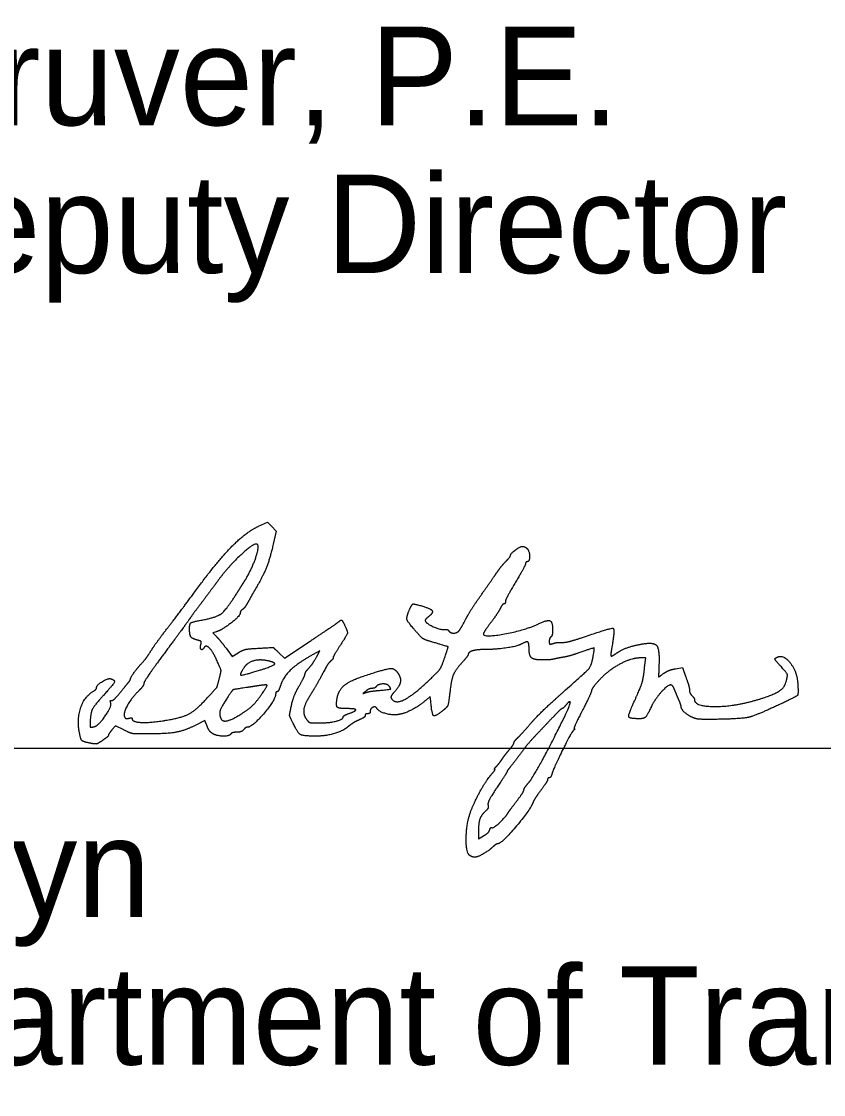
# Model space of a CAD drawing. Extents: x 0 to 34, y 0 to 22.
# Drawn here: x 25.648 to 26.788, y 7.199 to 8.723 of the extents above; entities that cross this region are included whole.
import ezdxf

# ---------------------------------------------------------------- set-up
doc = ezdxf.new("R2010")
doc.units = 0
doc.layers.add('SH_Data', color=7, linetype='Continuous')
doc.layers.add('SH_Text', color=7, linetype='Continuous')

msp = doc.modelspace()

# ---------------------------------------------------------------- linework, layer by layer
at = {"layer": 'SH_Data'}
msp.add_line((24.5, 7.691), (28, 7.691), dxfattribs=at)
at = {"layer": 'SH_Text'}
for points in [[(25.9853, 8.0062), (25.9979, 8.012), (26.0042, 8.0057), (26.0106, 7.9993), (26.0062, 7.9806)], [(25.9253, 7.8562), (25.9203, 7.8546), (25.9255, 7.8495)], [(26.0143, 7.8265), (26.0224, 7.8189), (26.0587, 7.843)], [(25.9392, 7.8328), (25.9477, 7.8213), (25.9565, 7.8265)], [(26.0682, 7.8212), (26.0726, 7.8292), (26.0671, 7.8263)], [(26.534, 7.8053), (26.5355, 7.8191), (26.5277, 7.8191)], [(26.5779, 7.8037), (26.5876, 7.8053), (26.5926, 7.7917)], [(26.23, 7.7576), (26.2293, 7.7644), (26.2234, 7.7593)], [(25.7937, 7.7169), (25.7822, 7.7227), (25.7771, 7.7169)], [(25.9123, 7.722), (25.909, 7.73), (25.8951, 7.7231)], [(26.2977, 7.5714), (26.2977, 7.5621), (26.3052, 7.5664)]]:
    msp.add_lwpolyline(points, dxfattribs=at)
for points in [[(25.8957, 7.9143), (25.9254, 7.9549), (25.9672, 7.9978), (25.9853, 8.0062)], [(25.9838, 7.9804), (25.9802, 7.984), (25.9416, 7.9483), (25.9262, 7.927)], [(25.9655, 7.9283), (25.9749, 7.9432), (25.9869, 7.9773), (25.9838, 7.9804)], [(26.0062, 7.9806), (26.0012, 7.9595), (25.992, 7.9359), (25.9826, 7.9199)], [(26.3433, 7.9643), (26.3433, 7.9671), (26.3565, 7.9774), (26.3602, 7.9775)], [(26.3602, 7.9775), (26.3623, 7.9775), (26.3652, 7.9762), (26.3668, 7.9747)], [(26.3668, 7.9747), (26.3703, 7.9712), (26.3707, 7.9559), (26.3673, 7.9559)], [(26.3367, 7.9562), (26.3403, 7.9598), (26.3433, 7.9634), (26.3433, 7.9643)], [(26.3229, 7.9389), (26.3269, 7.9448), (26.3331, 7.9525), (26.3367, 7.9562)], [(26.3649, 7.9534), (26.3649, 7.952), (26.3584, 7.9399), (26.3505, 7.9266)], [(26.3673, 7.9559), (26.366, 7.9559), (26.3649, 7.9548), (26.3649, 7.9534)], [(25.955, 7.9117), (25.9583, 7.9169), (25.963, 7.9244), (25.9655, 7.9283)], [(26.3013, 7.9079), (26.3092, 7.9192), (26.319, 7.9331), (26.3229, 7.9389)], [(25.8555, 7.8609), (25.8644, 7.8722), (25.8825, 7.8963), (25.8957, 7.9143)], [(25.9262, 7.927), (25.9226, 7.9221), (25.9132, 7.9094), (25.9053, 7.8989)], [(25.9826, 7.9199), (25.9791, 7.914), (25.9739, 7.9048), (25.971, 7.8995)], [(26.3505, 7.9266), (26.3426, 7.9132), (26.3361, 7.9008), (26.3361, 7.8991)], [(25.9053, 7.8989), (25.8974, 7.8884), (25.8893, 7.8774), (25.8873, 7.8745)], [(25.9052, 7.873), (25.9258, 7.8768), (25.9398, 7.8877), (25.955, 7.9117)], [(25.971, 7.8995), (25.9682, 7.8943), (25.9644, 7.8891), (25.9626, 7.888)], [(26.2799, 7.8743), (26.2837, 7.8816), (26.2933, 7.8967), (26.3013, 7.9079)], [(26.3361, 7.8991), (26.3361, 7.8973), (26.3352, 7.8959), (26.3341, 7.8959)], [(25.9593, 7.8826), (25.9593, 7.8788), (25.9335, 7.8588), (25.9253, 7.8562)], [(25.9626, 7.888), (25.9608, 7.887), (25.9593, 7.8845), (25.9593, 7.8826)], [(26.209, 7.8568), (26.1975, 7.8698), (26.1953, 7.8766), (26.1992, 7.8862)], [(26.1992, 7.8862), (26.203, 7.8952), (26.2061, 7.8963), (26.2188, 7.8925)], [(26.2188, 7.8925), (26.2308, 7.889), (26.2337, 7.8828), (26.226, 7.8769)], [(26.3288, 7.8893), (26.3271, 7.8857), (26.3209, 7.8766), (26.3152, 7.8691)], [(26.3341, 7.8959), (26.333, 7.8959), (26.3306, 7.893), (26.3288, 7.8893)], [(25.8873, 7.8745), (25.8853, 7.8715), (25.87, 7.8506), (25.8532, 7.8279)], [(25.8873, 7.8609), (25.8873, 7.8677), (25.8914, 7.8705), (25.9052, 7.873)], [(26.0587, 7.843), (26.0786, 7.8563), (26.0962, 7.8682), (26.0978, 7.8695)], [(26.0978, 7.8695), (26.1023, 7.8733), (26.1047, 7.8724), (26.1077, 7.8658)], [(26.226, 7.8769), (26.2233, 7.8749), (26.2218, 7.872), (26.2228, 7.8707)], [(26.2228, 7.8707), (26.2254, 7.8669), (26.2453, 7.8587), (26.25, 7.8595)], [(26.2706, 7.8581), (26.2719, 7.8598), (26.2761, 7.8671), (26.2799, 7.8743)], [(26.3152, 7.8691), (26.3096, 7.8617), (26.3049, 7.8544), (26.3049, 7.8531)], [(26.3825, 7.8673), (26.3955, 7.8735), (26.4033, 7.8703), (26.4033, 7.8589)], [(25.834, 7.8315), (25.837, 7.8363), (25.8467, 7.8495), (25.8555, 7.8609)], [(25.8983, 7.8445), (25.8911, 7.8463), (25.8873, 7.852), (25.8873, 7.8609)], [(26.1077, 7.8658), (26.1121, 7.8562), (26.1111, 7.8521), (26.1009, 7.8362)], [(26.2325, 7.8416), (26.2217, 7.8447), (26.2168, 7.8479), (26.209, 7.8568)], [(26.25, 7.8595), (26.2522, 7.8599), (26.2548, 7.859), (26.2556, 7.8577)], [(26.2556, 7.8577), (26.2578, 7.8542), (26.2678, 7.8545), (26.2706, 7.8581)], [(26.3049, 7.8531), (26.3049, 7.8478), (26.3645, 7.8587), (26.3825, 7.8673)], [(26.4033, 7.8589), (26.4033, 7.8544), (26.4022, 7.85), (26.4009, 7.8491)], [(26.4456, 7.8482), (26.486, 7.8621), (26.4919, 7.8605), (26.4878, 7.8366)], [(25.9034, 7.8382), (25.9043, 7.8418), (25.9031, 7.8433), (25.8983, 7.8445)], [(25.9077, 7.8335), (25.9052, 7.8296), (25.902, 7.8331), (25.9034, 7.8382)], [(25.9255, 7.8495), (25.9283, 7.8467), (25.9345, 7.8392), (25.9392, 7.8328)], [(26.2493, 7.8179), (26.255, 7.8347), (26.2546, 7.8353), (26.2325, 7.8416)], [(26.3583, 7.8385), (26.3527, 7.8355), (26.3225, 7.8311), (26.3075, 7.8311)], [(26.3697, 7.8338), (26.3697, 7.8411), (26.366, 7.8427), (26.3583, 7.8385)], [(26.4009, 7.8491), (26.3996, 7.8483), (26.3985, 7.8455), (26.3985, 7.8428)], [(26.3985, 7.8428), (26.3985, 7.8389), (26.3995, 7.8383), (26.4039, 7.8397)], [(26.4039, 7.8397), (26.4069, 7.8407), (26.4127, 7.8413), (26.4168, 7.8412)], [(26.4168, 7.8412), (26.421, 7.841), (26.4339, 7.8442), (26.4456, 7.8482)], [(26.4938, 7.8257), (26.501, 7.8308), (26.5192, 7.8371), (26.5329, 7.8393)], [(26.5329, 7.8393), (26.5476, 7.8416), (26.5552, 7.8311), (26.5544, 7.8099)], [(25.8177, 7.8096), (25.8243, 7.8169), (25.8285, 7.8227), (25.834, 7.8315)], [(25.8532, 7.8279), (25.8364, 7.8053), (25.8226, 7.7851), (25.8225, 7.7831)], [(25.9265, 7.8149), (25.9203, 7.8285), (25.9106, 7.8382), (25.9077, 7.8335)], [(25.9565, 7.8265), (25.963, 7.8304), (25.9706, 7.8321), (25.9857, 7.8329)], [(25.9857, 7.8329), (26.006, 7.8341), (26.0062, 7.8341), (26.0143, 7.8265)], [(26.0671, 7.8263), (26.0437, 7.8137), (26.021, 7.793), (26.0168, 7.7806)], [(26.1009, 7.8362), (26.0956, 7.8281), (26.0913, 7.8205), (26.0913, 7.8194)], [(26.2833, 7.824), (26.2833, 7.8231), (26.2791, 7.8177), (26.2739, 7.8119)], [(26.3075, 7.8311), (26.296, 7.8311), (26.2833, 7.8274), (26.2833, 7.824)], [(26.389, 7.8162), (26.3766, 7.8162), (26.3697, 7.8225), (26.3697, 7.8338)], [(26.4403, 7.8262), (26.4325, 7.8235), (26.4229, 7.8208), (26.4189, 7.8202)], [(26.4609, 7.8216), (26.463, 7.8331), (26.4613, 7.8335), (26.4403, 7.8262)], [(26.4878, 7.8366), (26.4865, 7.829), (26.4857, 7.8224), (26.4862, 7.8219)], [(26.4862, 7.8219), (26.4867, 7.8214), (26.4901, 7.8231), (26.4938, 7.8257)], [(25.8033, 7.7891), (25.8033, 7.7908), (25.8124, 7.8038), (25.8177, 7.8096)], [(25.9298, 7.7903), (25.9323, 7.8002), (25.932, 7.8024), (25.9265, 7.8149)], [(25.9975, 7.8152), (25.9866, 7.8174), (25.9693, 7.8123), (25.9649, 7.8057)], [(25.9869, 7.8017), (26.0061, 7.8076), (26.0101, 7.8127), (25.9975, 7.8152)], [(26.0554, 7.8031), (26.0608, 7.8091), (26.0633, 7.8127), (26.0682, 7.8212)], [(26.0877, 7.8144), (26.0858, 7.8128), (26.0827, 7.8086), (26.0809, 7.8051)], [(26.0913, 7.8194), (26.0913, 7.8182), (26.0897, 7.816), (26.0877, 7.8144)], [(26.231, 7.7906), (26.2414, 7.8006), (26.2455, 7.8068), (26.2493, 7.8179)], [(26.2739, 7.8119), (26.2655, 7.8024), (26.2597, 7.7899), (26.2581, 7.7771)], [(26.4057, 7.8176), (26.4024, 7.8168), (26.3949, 7.8162), (26.389, 7.8162)], [(26.4189, 7.8202), (26.4149, 7.8195), (26.409, 7.8184), (26.4057, 7.8176)], [(26.4161, 7.7686), (26.4516, 7.8002), (26.4585, 7.8083), (26.4609, 7.8216)], [(26.5277, 7.8191), (26.515, 7.8191), (26.4812, 7.8007), (26.4691, 7.7872)], [(26.5544, 7.8099), (26.5537, 7.7915), (26.5536, 7.7918), (26.5613, 7.7973)], [(26.7245, 7.8105), (26.7192, 7.8162), (26.719, 7.8189), (26.7236, 7.8206)], [(26.7236, 7.8206), (26.7322, 7.8239), (26.7506, 7.799), (26.7516, 7.7827)], [(26.7336, 7.7814), (26.7376, 7.7932), (26.736, 7.7981), (26.7245, 7.8105)], [(25.9649, 7.8057), (25.9579, 7.795), (25.9625, 7.7942), (25.9869, 7.8017)], [(26.0429, 7.779), (26.0473, 7.7867), (26.0512, 7.7943), (26.0514, 7.7961)], [(26.0514, 7.7961), (26.0517, 7.7978), (26.0535, 7.801), (26.0554, 7.8031)], [(26.0809, 7.8051), (26.0727, 7.7897), (26.0649, 7.7759), (26.0588, 7.7662)], [(26.0971, 7.7623), (26.0992, 7.7736), (26.1154, 7.787), (26.1347, 7.7934)], [(26.1347, 7.7934), (26.1665, 7.804), (26.1799, 7.8044), (26.185, 7.7949)], [(26.185, 7.7949), (26.1882, 7.7889), (26.1848, 7.7775), (26.1774, 7.7696)], [(26.5194, 7.7575), (26.5284, 7.7774), (26.5324, 7.7906), (26.534, 7.8053)], [(26.5613, 7.7973), (26.5651, 7.8), (26.5726, 7.8029), (26.5779, 7.8037)], [(26.5926, 7.7917), (26.5954, 7.7843), (26.5977, 7.7761), (26.5977, 7.7736)], [(25.7506, 7.7718), (25.7532, 7.7734), (25.7553, 7.7758), (25.7553, 7.7771)], [(25.7553, 7.7771), (25.7554, 7.7809), (25.7721, 7.7908), (25.7759, 7.7894)], [(25.7759, 7.7894), (25.7819, 7.7871), (25.7796, 7.7822), (25.7653, 7.7663)], [(25.7888, 7.7699), (25.7941, 7.7765), (25.7996, 7.7832), (25.8009, 7.7848)], [(25.8009, 7.7848), (25.8022, 7.7864), (25.8033, 7.7884), (25.8033, 7.7891)], [(25.8225, 7.7831), (25.8224, 7.7812), (25.8191, 7.7763), (25.8151, 7.7724)], [(25.9101, 7.7598), (25.9262, 7.7774), (25.9265, 7.7779), (25.9298, 7.7903)], [(25.9677, 7.7769), (25.9499, 7.7743), (25.9479, 7.7732), (25.9406, 7.762)], [(25.9851, 7.7796), (25.9795, 7.7787), (25.9717, 7.7775), (25.9677, 7.7769)], [(25.9901, 7.7679), (25.9979, 7.7793), (25.997, 7.7814), (25.9851, 7.7796)], [(26.0168, 7.7806), (26.0151, 7.7754), (26.0128, 7.7711), (26.0117, 7.7711)], [(26.032, 7.7512), (26.0336, 7.7589), (26.0385, 7.7714), (26.0429, 7.779)], [(26.1468, 7.7759), (26.1445, 7.7759), (26.1405, 7.7742), (26.138, 7.7721)], [(26.1523, 7.7781), (26.1516, 7.7769), (26.1491, 7.7759), (26.1468, 7.7759)], [(26.1708, 7.7792), (26.168, 7.7825), (26.1546, 7.7817), (26.1523, 7.7781)], [(26.1549, 7.7728), (26.1716, 7.7743), (26.174, 7.7753), (26.1708, 7.7792)], [(26.174, 7.7617), (26.1793, 7.7531), (26.2061, 7.7666), (26.231, 7.7906)], [(26.2581, 7.7771), (26.2553, 7.7546), (26.2536, 7.7492), (26.2479, 7.7447)], [(26.4691, 7.7872), (26.4632, 7.7807), (26.4585, 7.7741), (26.4585, 7.7726)], [(26.5709, 7.7807), (26.5666, 7.7807), (26.5483, 7.7602), (26.5436, 7.7501)], [(26.5765, 7.7741), (26.575, 7.7778), (26.5725, 7.7807), (26.5709, 7.7807)], [(26.6847, 7.7571), (26.7084, 7.7634), (26.7314, 7.7748), (26.7336, 7.7814)], [(26.7516, 7.7827), (26.7526, 7.7674), (26.7499, 7.7643), (26.7265, 7.7533)], [(25.7304, 7.7155), (25.7275, 7.734), (25.7382, 7.764), (25.7506, 7.7718)], [(25.7653, 7.7663), (25.7516, 7.7511), (25.7466, 7.741), (25.746, 7.7272)], [(25.7765, 7.7586), (25.7779, 7.7583), (25.7834, 7.7633), (25.7888, 7.7699)], [(25.8151, 7.7724), (25.8053, 7.7628), (25.7929, 7.7407), (25.7947, 7.736)], [(25.9406, 7.762), (25.9324, 7.7493), (25.9292, 7.7395), (25.9315, 7.7337)], [(25.9602, 7.7392), (25.9714, 7.7462), (25.9824, 7.7567), (25.9901, 7.7679)], [(26.0097, 7.7681), (26.0095, 7.7596), (25.9764, 7.7207), (25.9693, 7.7207)], [(26.0117, 7.7711), (26.0106, 7.7711), (26.0097, 7.7698), (26.0097, 7.7681)], [(26.0588, 7.7662), (26.0508, 7.7536), (26.0486, 7.7384), (26.0537, 7.7316)], [(26.1106, 7.7471), (26.0991, 7.7471), (26.0951, 7.7517), (26.0971, 7.7623)], [(26.138, 7.7721), (26.1334, 7.7684), (26.1334, 7.7684), (26.1381, 7.77)], [(26.1381, 7.77), (26.1407, 7.771), (26.1483, 7.7722), (26.1549, 7.7728)], [(26.1774, 7.7696), (26.1746, 7.7667), (26.1731, 7.7631), (26.174, 7.7617)], [(26.372, 7.7259), (26.3792, 7.7343), (26.399, 7.7535), (26.4161, 7.7686)], [(26.4585, 7.7726), (26.4585, 7.771), (26.4525, 7.7581), (26.4453, 7.744)], [(26.5824, 7.76), (26.5806, 7.7641), (26.578, 7.7705), (26.5765, 7.7741)], [(26.5977, 7.7736), (26.5977, 7.7711), (26.5993, 7.7675), (26.6013, 7.7655)], [(26.6013, 7.7655), (26.6033, 7.7635), (26.6049, 7.7608), (26.6049, 7.7595)], [(25.7509, 7.7212), (25.7572, 7.7221), (25.7773, 7.7505), (25.7753, 7.7557)], [(25.7753, 7.7557), (25.7745, 7.7577), (25.7751, 7.759), (25.7765, 7.7586)], [(25.8536, 7.7305), (25.8763, 7.7342), (25.8959, 7.7444), (25.9101, 7.7598)], [(26.034, 7.7272), (26.0296, 7.7363), (26.0294, 7.7385), (26.032, 7.7512)], [(26.114, 7.7402), (26.1243, 7.7439), (26.1227, 7.7471), (26.1106, 7.7471)], [(26.1536, 7.7473), (26.1516, 7.7506), (26.1441, 7.7474), (26.1441, 7.7433)], [(26.1849, 7.7388), (26.1763, 7.7372), (26.1565, 7.7426), (26.1536, 7.7473)], [(26.2234, 7.7593), (26.214, 7.7511), (26.194, 7.7405), (26.1849, 7.7388)], [(26.2479, 7.7447), (26.2362, 7.7355), (26.2318, 7.7386), (26.23, 7.7576)], [(26.3694, 7.6421), (26.3771, 7.6508), (26.4303, 7.7545), (26.4282, 7.7566)], [(26.4167, 7.7471), (26.416, 7.7471), (26.412, 7.7436), (26.4079, 7.7393)], [(26.4225, 7.7525), (26.4201, 7.7496), (26.4175, 7.7471), (26.4167, 7.7471)], [(26.4282, 7.7566), (26.4275, 7.7573), (26.4249, 7.7555), (26.4225, 7.7525)], [(26.5267, 7.7327), (26.5122, 7.7327), (26.5106, 7.7382), (26.5194, 7.7575)], [(26.5436, 7.7501), (26.5379, 7.7377), (26.5331, 7.7327), (26.5267, 7.7327)], [(26.5858, 7.7504), (26.5857, 7.7515), (26.5842, 7.7558), (26.5824, 7.76)], [(26.6014, 7.7348), (26.5944, 7.7381), (26.5859, 7.7465), (26.5858, 7.7504)], [(26.6049, 7.7595), (26.6049, 7.7509), (26.6555, 7.7495), (26.6847, 7.7571)], [(26.7265, 7.7533), (26.6917, 7.737), (26.6707, 7.7322), (26.6313, 7.7318)], [(25.7947, 7.736), (25.7956, 7.7336), (25.7979, 7.7327), (25.8009, 7.7334)], [(25.8009, 7.7334), (25.8035, 7.7341), (25.8057, 7.7338), (25.8057, 7.7327)], [(25.8057, 7.7327), (25.8057, 7.7281), (25.8313, 7.7269), (25.8536, 7.7305)], [(25.9315, 7.7337), (25.9335, 7.7284), (25.9471, 7.731), (25.9602, 7.7392)], [(26.0537, 7.7316), (26.0566, 7.7277), (26.0601, 7.7268), (26.0713, 7.7268)], [(26.0713, 7.7268), (26.0853, 7.7267), (26.1057, 7.7318), (26.1057, 7.7354)], [(26.1057, 7.7354), (26.1057, 7.7364), (26.1094, 7.7386), (26.114, 7.7402)], [(26.1315, 7.7326), (26.1242, 7.7293), (26.1165, 7.7247), (26.1123, 7.7212)], [(26.1369, 7.7375), (26.1369, 7.7361), (26.1345, 7.7339), (26.1315, 7.7326)], [(26.1405, 7.7399), (26.1385, 7.7399), (26.1369, 7.7388), (26.1369, 7.7375)], [(26.1441, 7.7433), (26.1441, 7.7414), (26.1425, 7.7399), (26.1405, 7.7399)], [(26.4079, 7.7393), (26.4038, 7.735), (26.3933, 7.724), (26.3845, 7.7147)], [(26.4453, 7.744), (26.438, 7.7299), (26.4329, 7.7183), (26.4339, 7.7183)], [(26.6313, 7.7318), (26.6164, 7.7316), (26.6061, 7.7326), (26.6014, 7.7348)], [(25.747, 7.6978), (25.7361, 7.6998), (25.7323, 7.7039), (25.7304, 7.7155)], [(25.746, 7.7272), (25.7458, 7.7216), (25.7466, 7.7205), (25.7509, 7.7212)], [(25.7771, 7.7169), (25.7744, 7.7137), (25.7721, 7.7103), (25.7721, 7.7093)], [(25.8245, 7.7111), (25.8089, 7.7111), (25.803, 7.7122), (25.7937, 7.7169)], [(25.8951, 7.7231), (25.8796, 7.7154), (25.8544, 7.7111), (25.8245, 7.7111)], [(25.9205, 7.7113), (25.9179, 7.7128), (25.9142, 7.7175), (25.9123, 7.722)], [(25.9641, 7.7171), (25.9625, 7.7152), (25.9581, 7.7135), (25.9543, 7.7135)], [(25.9693, 7.7207), (25.9681, 7.7207), (25.9657, 7.7191), (25.9641, 7.7171)], [(26.0658, 7.708), (26.0483, 7.7081), (26.0413, 7.7123), (26.034, 7.7272)], [(26.1123, 7.7212), (26.1046, 7.7149), (26.0803, 7.7079), (26.0658, 7.708)], [(26.3535, 7.7055), (26.3565, 7.7083), (26.3648, 7.7175), (26.372, 7.7259)], [(26.4331, 7.7165), (26.4304, 7.7147), (26.4052, 7.6637), (26.4022, 7.6541)], [(26.4339, 7.7183), (26.4349, 7.7183), (26.4345, 7.7175), (26.4331, 7.7165)], [(25.7637, 7.7019), (25.7572, 7.6974), (25.7536, 7.6965), (25.747, 7.6978)], [(25.7721, 7.7093), (25.7721, 7.7083), (25.7683, 7.705), (25.7637, 7.7019)], [(25.9461, 7.7111), (25.9441, 7.7079), (25.9266, 7.7081), (25.9205, 7.7113)], [(25.9543, 7.7135), (25.9506, 7.7135), (25.9469, 7.7125), (25.9461, 7.7111)], [(26.3481, 7.6983), (26.3482, 7.6994), (26.3506, 7.7027), (26.3535, 7.7055)], [(26.3845, 7.7147), (26.3757, 7.7054), (26.3658, 7.6942), (26.3625, 7.6897)], [(26.3313, 7.6751), (26.3333, 7.6782), (26.3379, 7.6842), (26.3415, 7.6884)], [(26.3625, 7.6897), (26.3544, 7.6788), (26.3439, 7.665), (26.3409, 7.6614)], [(26.3415, 7.6884), (26.3451, 7.6927), (26.3481, 7.6971), (26.3481, 7.6983)], [(26.3235, 7.6651), (26.3258, 7.6676), (26.3293, 7.6721), (26.3313, 7.6751)], [(26.2875, 7.6027), (26.2934, 7.6176), (26.3105, 7.6475), (26.3176, 7.6553)], [(26.3176, 7.6553), (26.3203, 7.6583), (26.3218, 7.6607), (26.3209, 7.6607)], [(26.3209, 7.6607), (26.32, 7.6607), (26.3212, 7.6627), (26.3235, 7.6651)], [(26.3385, 7.6576), (26.3385, 7.657), (26.3322, 7.6471), (26.3244, 7.6354)], [(26.3409, 7.6614), (26.3396, 7.6598), (26.3385, 7.6581), (26.3385, 7.6576)], [(26.4022, 7.6541), (26.4013, 7.6512), (26.3996, 7.6487), (26.3983, 7.6487)], [(26.3625, 7.6318), (26.3625, 7.6331), (26.3656, 7.6377), (26.3694, 7.6421)], [(26.3961, 7.6462), (26.3961, 7.6449), (26.3918, 7.6381), (26.3866, 7.6312)], [(26.3983, 7.6487), (26.3971, 7.6487), (26.3961, 7.6476), (26.3961, 7.6462)], [(26.3244, 7.6354), (26.3158, 7.6224), (26.3108, 7.6126), (26.3115, 7.6099)], [(26.3523, 7.6159), (26.3579, 7.6233), (26.3625, 7.6304), (26.3625, 7.6318)], [(26.3866, 7.6312), (26.3814, 7.6243), (26.3763, 7.6163), (26.3752, 7.6135)], [(26.3115, 7.6099), (26.3122, 7.6074), (26.3106, 7.6038), (26.3078, 7.6013)], [(26.3752, 7.6135), (26.3716, 7.6036), (26.3304, 7.5551), (26.3257, 7.5551)], [(26.3397, 7.5987), (26.341, 7.6008), (26.3467, 7.6086), (26.3523, 7.6159)], [(26.2857, 7.5383), (26.2798, 7.5421), (26.281, 7.5864), (26.2875, 7.6027)], [(26.3078, 7.6013), (26.3019, 7.5961), (26.2977, 7.5838), (26.2977, 7.5714)], [(26.3169, 7.5779), (26.3188, 7.5768), (26.3355, 7.5919), (26.3397, 7.5987)], [(26.3139, 7.5749), (26.3145, 7.5772), (26.3159, 7.5786), (26.3169, 7.5779)], [(26.3052, 7.5664), (26.3094, 7.5688), (26.3133, 7.5726), (26.3139, 7.5749)], [(26.3183, 7.5506), (26.3121, 7.5449), (26.2961, 7.5359), (26.2922, 7.536)], [(26.3257, 7.5551), (26.3243, 7.5551), (26.321, 7.5531), (26.3183, 7.5506)], [(26.2922, 7.536), (26.2906, 7.536), (26.2877, 7.537), (26.2857, 7.5383)]]:
    msp.add_open_spline(points, degree=2, dxfattribs=at)

# ---------------------------------------------------------------- texts
for s, p in [('Douglas A. Gruver, P.E.', (24.5, 8.576)), ('District       Deputy Director', (24.5, 8.366)), ('Pamela Boratyn', (24.5, 7.451)), ('Director, Department of Transportation', (24.5, 7.241))]:
    msp.add_text(s, height=0.14, dxfattribs=at).set_placement(p)

doc.saveas('drawing.dxf')
